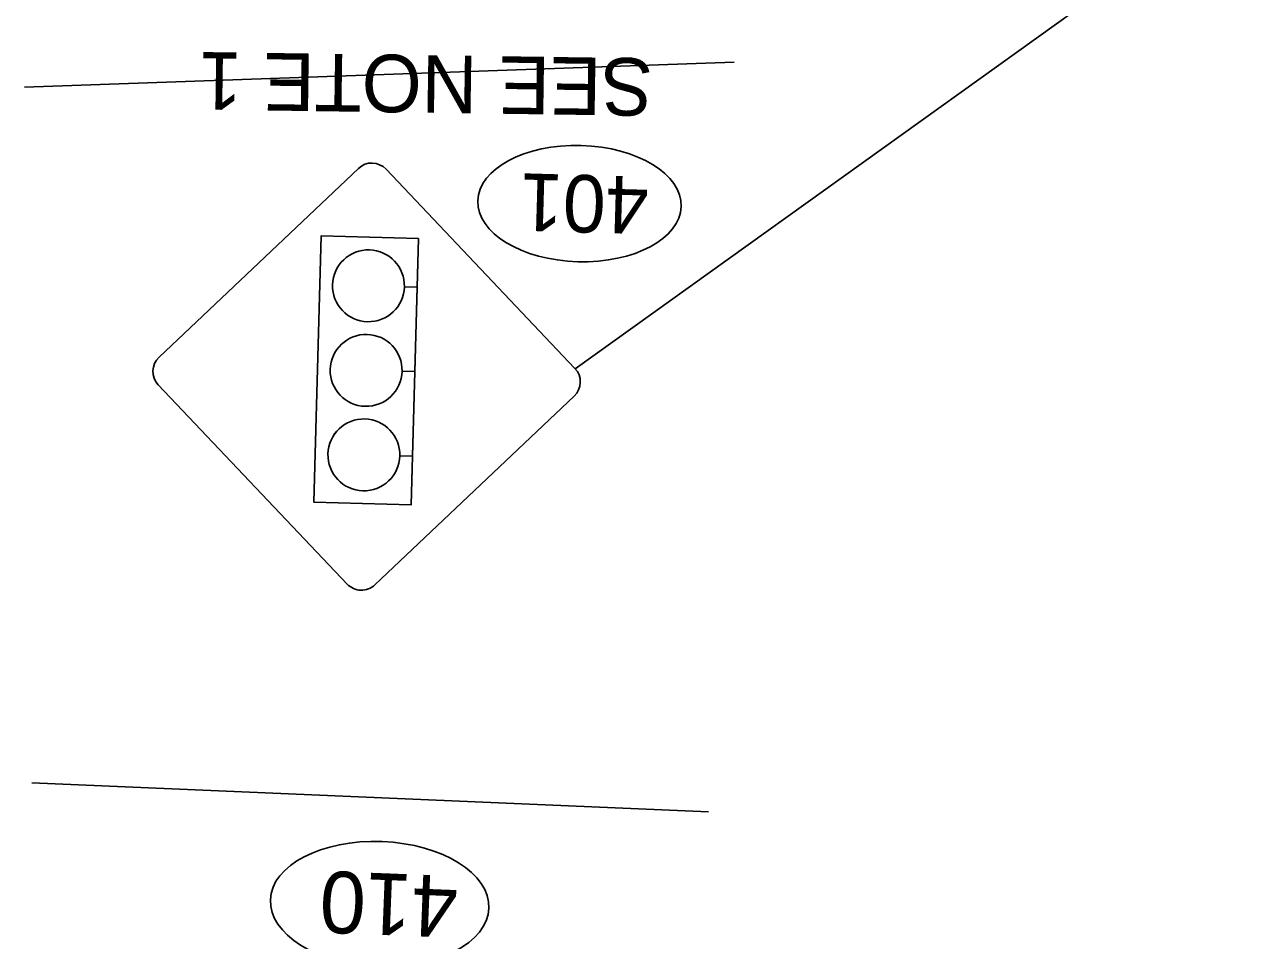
# Model space of a CAD drawing. Extents: x 2096670 to 2098561, y 684033 to 689893.
# Drawn here: x 2097358.5 to 2097615, y 686268.1 to 686459 of the extents above; entities that cross this region are included whole.
import ezdxf

# ---------------------------------------------------------------- set-up
doc = ezdxf.new("R2010")
doc.units = 0
for name, color, linetype in [('Default', 7, 'Continuous'), ('Prop DSN Text', 7, 'Continuous'), ('Prop Sign E One Way_Right CELL', 7, 'Continuous'), ('Prop Sign E Right Lane Must Turn Right CELL', 7, 'Continuous'), ('Scratch_Level_3', 7, 'Continuous')]:
    doc.layers.add(name, color=color, linetype=linetype)

msp = doc.modelspace()

# ---------------------------------------------------------------- linework, layer by layer
at = {"layer": 'Default'}
for p, q in [((2097473.27, 686387.28), (2097662.2, 686522.83)), ((2097428.07, 686429.04), (2097386.53, 686389.68)), ((2097473.19, 686387.35), (2097433.83, 686428.89)), ((2097386.38, 686383.92), (2097425.74, 686342.38)), ((2097431.51, 686342.23), (2097473.04, 686381.59)), ((2097436.71, 686369.12), (2097436.71, 686369.12)), ((2097436.71, 686369.12), (2097436.71, 686369.12))]:
    msp.add_line(p, q, dxfattribs=at)
msp.add_lwpolyline([(2097418.82, 686359.46), (2097439.08, 686358.91), (2097440.58, 686414.43), (2097420.31, 686414.97)], close=True, dxfattribs=at)
for points in [[(2097437.66, 686404.37), (2097440.3, 686404.3), (2097440.58, 686414.43), (2097420.31, 686414.97), (2097418.82, 686359.46), (2097439.08, 686358.91), (2097439.36, 686369.05), (2097436.71, 686369.12)], [(2097437.66, 686404.37), (2097440.3, 686404.3), (2097440.58, 686414.43), (2097420.31, 686414.97), (2097418.82, 686359.46), (2097439.08, 686358.91), (2097439.36, 686369.05), (2097436.71, 686369.12)], [(2097437.19, 686386.74), (2097439.83, 686386.67), (2097440.3, 686404.3), (2097437.66, 686404.37)], [(2097437.19, 686386.74), (2097439.83, 686386.67), (2097440.3, 686404.3), (2097437.66, 686404.37)], [(2097436.71, 686369.12), (2097439.36, 686369.05), (2097439.83, 686386.67), (2097437.19, 686386.74)], [(2097436.71, 686369.12), (2097439.36, 686369.05), (2097439.83, 686386.67), (2097437.19, 686386.74)]]:
    msp.add_lwpolyline(points, dxfattribs=at)
for centre, major_axis, start_param, end_param in [((2097430.87, 686426.08), (0.11, 4.08), 5.497787, 7.068583), ((2097430.17, 686404.57), (0.2, 7.49), 4.712482, 10.995574), ((2097430.17, 686404.57), (0.2, 7.49), 4.712482, 10.995574), ((2097429.69, 686386.94), (0.2, 7.49), 4.712482, 10.995574), ((2097429.69, 686386.94), (0.2, 7.49), 4.712482, 10.995574), ((2097389.34, 686386.72), (0.11, 4.08), 0.785398, 2.356194), ((2097470.23, 686384.55), (0.11, 4.08), 3.926991, 5.497787), ((2097429.22, 686369.32), (0.2, 7.49), 4.712482, 10.995574), ((2097429.22, 686369.32), (0.2, 7.49), 4.712482, 10.995574), ((2097428.7, 686345.19), (0.11, 4.08), 2.356194, 3.926991)]:
    msp.add_ellipse(centre, major_axis=major_axis, ratio=0.999984, start_param=start_param, end_param=end_param, dxfattribs=at)
for centre in [(2097430.17, 686404.57), (2097430.17, 686404.57), (2097429.69, 686386.94), (2097429.69, 686386.94), (2097429.22, 686369.32)]:
    msp.add_ellipse(centre, major_axis=(0.2, 7.49), ratio=0.999984, dxfattribs=at)
at = {"layer": 'Prop Sign E One Way_Right CELL'}
msp.add_ellipse((2097474.15, 686421.71), major_axis=(21.21, -0.6), ratio=0.571429, dxfattribs=at)
at = {"layer": 'Prop Sign E Right Lane Must Turn Right CELL'}
msp.add_ellipse((2097432.5, 686275.69), major_axis=(22.77, -0.89), ratio=0.571429, dxfattribs=at)
at = {"layer": 'Scratch_Level_3'}
for p, q in [((2097358.52, 686445.98), (2097506.36, 686451.22)), ((2097360.02, 686300.92), (2097501, 686294.87))]:
    msp.add_line(p, q, dxfattribs=at)

# ---------------------------------------------------------------- texts
at = {"layer": 'Prop DSN Text'}
msp.add_text('SEE NOTE 1', height=12, rotation=179.1923, dxfattribs=at).set_placement((2097489.49, 686451.99))
at = {"layer": 'Prop Sign E One Way_Right CELL'}
msp.add_text('401', height=11.98, rotation=178.3897, dxfattribs=at).set_placement((2097488.68, 686427.29))
at = {"layer": 'Prop Sign E Right Lane Must Turn Right CELL'}
msp.add_text('410', height=12.865, rotation=177.7582, dxfattribs=at).set_placement((2097448.99, 686281.48))

doc.saveas('drawing.dxf')
